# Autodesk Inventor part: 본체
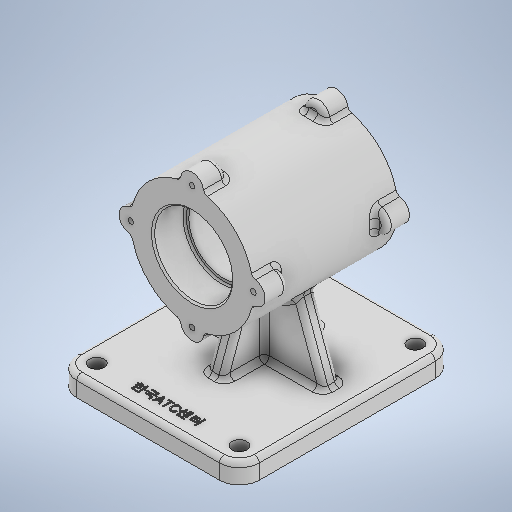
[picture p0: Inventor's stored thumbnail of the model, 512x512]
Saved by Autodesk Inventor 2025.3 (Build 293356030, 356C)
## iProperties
Created: 2025-08
Part Number: 본체
Material: 일반
Document SubType Name: Modeling
Designer: user
Density: 1 g/cm^3
Appearance: 기본값
Author: user
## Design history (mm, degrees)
sketch "스케치2"
  geometry: L1 (43, 65)-(-43, 65); L2 (-55, 53)-(-55, -53); L3 (-43, -65)-(43, -65); L4 (55, -53)-(55, 53); L5 (55, 65)-(-55, -65); L6 (-55, 65)-(55, -65); A1 r 12 centre (43, 53) between (55, 53) and (43, 65); A2 r 12 centre (-43, 53) between (-43, 65) and (-55, 53); A3 r 12 centre (43, -53) between (43, -65) and (55, -53); A4 r 12 centre (-43, -53) between (-55, -53) and (-43, -65); 1 further point
  constraints: 12 end point, 8 point on circle, 8 point on line, 8 tangent, 4 centre point, 3 equal radius, 2 midpoint, 2 parallel, 1 horizontal, 1 perpendicular
  dimensions: "d0" = 130 distance between parallel lines of L3 L1; "d1" = 110 distance between parallel lines of L4 L2; "d2" = 12 radius of A1
extrude "돌출1" new body sketch "스케치2" distance "d3" = 12; taper "d4" = 0 deg
sketch "스케치3"
  geometry: L1 (-43, -53)-(43, -53); L2 (43, -53)-(43, 53); L3 (43, 53)-(-43, 53); L4 (-43, 53)-(-43, -53); L5 (-43, -53)-(43, 53); L6 (43, -53)-(-43, 53); 1 further point
  constraints: 12 end point, 2 midpoint, 2 parallel, 1 horizontal, 1 perpendicular
  dimensions: "d5" = 86 distance of L3.end L2.end; "d6" = 106 distance of L2.end L1.end
hole "구멍1" sketch "스케치3" at (43, -53), (-43, -53), (-43, 53), (43, 53) diameter "d7" = 9; stored, may be unused: countersink angle "d11" = 90 deg, drill point angle "d13" = 118 deg; dims "d8" = 6, "d9" = 4, "d10" = 2, "d12" = 8
sketch "스케치4"
  geometry: L1 (119, 38.5)-(82, 38.5); L2 (82, 38.5)-(82, -48.5); L3 (82, -48.5)-(119, -48.5); L4 (119, -48.5)-(119, 38.5); L5 (0, 53)-(0, -53) reference; L6 (0, 65)-(12, 65) reference; L7 (82, 38.5)-(105.5, 38.5); L8 (105.5, 38.5)-(105.5, 19.5); L9 (105.5, 19.5)-(82, 19.5); L10 (82, 19.5)-(82, 38.5); L11 (82, -48.5)-(105.5, -48.5); L12 (105.5, -48.5)-(105.5, -29.5); L13 (105.5, -29.5)-(82, -29.5); L14 (82, -29.5)-(82, -48.5); L15 (82, 19.5)-(103, 19.5); L16 (103, 19.5)-(103, -29.5); L17 (103, -29.5)-(82, -29.5); L18 (82, -29.5)-(82, 19.5); 6 further points
  constraints: 32 end point, 8 parallel, 4 horizontal, 4 perpendicular, 2 midpoint, 1 point on line
  dimensions: "d14" = 37 distance of L3.end L2.end; "d15" = 87 distance of L2.end L1.end; "d16" = 82 distance between parallel lines of L5 L2; "d17" = 70 vertical distance of point (6, 65) point (119, -5); "d18" = 23.5 distance of L8.end L9.end; "d19" = 19 distance of L7.end L8.end; "d20" = 23.5 distance of L13.end L12.end; "d21" = 19 distance of L12.end L11.end; "d22" = 21 distance of L16.end L17.end
revolve "회전1" sketch "스케치4" stored, may be unused: angle "d23" = 90 deg
sketch "스케치5"
  geometry: L1 (0, 0)-(0, 37); C1 r 7 at (0, 37); C2 r 7 at (-37, 0); C3 r 7 at (0, -37); C4 r 7 at (37, 0); 2 further points
  constraints: 4 centre point, 2 end point, 1 coincident, 1 vertical, 1 vertical alignment, 10 other
  dimensions: "d25" = 0 distance from line of point (0, 0) L1; "d26" = 0 distance of L1.start point (0, 0); "d31" = 14 diameter of C1; "d34" = 360 deg dimension on L1.start C1.centre (derived)
extrude "돌출2" join sketch "스케치5" distance "d36" = 14; taper "d37" = 0 deg
sketch "스케치7"
  geometry: A1 r 7 centre (0, 0) between (6.969, -0.662) and (-6.969, -0.662) reference; A2 r 7 centre (37, -37) between (36.338, -43.969) and (36.338, -30.031) reference; A3 r 7 centre (0, -74) between (-6.969, -73.338) and (6.969, -73.338) reference; A4 r 7 centre (-37, -37) between (-36.338, -30.031) and (-36.338, -43.969) reference; 1 further point
hole "구멍2" sketch "스케치7" at (-37, -37), (0, -74), (0, 0), (37, -37) diameter "d38" = 3.242; stored, may be unused: countersink angle "d42" = 90 deg, drill point angle "d44" = 118 deg; dims "d39" = 8, "d40" = 4, "d41" = 2, "d43" = 10
node "작업 평면1"
sketch "스케치8"
  geometry: L1 (-43, -65)-(43, -65) reference; L2 (0, -65)-(0, 5); L3 (0, -65)-(70, -65); L4 (-5, 0)-(5, 0); L5 (5, 0)-(5, 10); L6 (5, 10)-(-5, 10); L7 (-5, 10)-(-5, 0); L8 (-5, 0)-(5, 10); L9 (5, 0)-(-5, 10); 1 further point
  constraints: 16 end point, 3 midpoint, 2 horizontal, 2 parallel, 2 perpendicular, 1 vertical
  dimensions: "d46" = 70 distance of L2.start L2.end; "d47" = 90 deg angle of L3 L2 (derived); "d48" = 10 distance of L6.end L5.end; "d49" = 10 distance of L5.end L4.end
extrude "돌출3" join sketch "스케치8" stored distance "d50" = 0; taper "d51" = 0 deg
node "작업 평면2"
sketch "스케치12"
  geometry: L1 (55, 12)-(43, 12) reference; L2 (55, 12)-(41, 12); L3 (38.5, 12)-(47.5, 12) reference; L4 (41, 12)-(25.336, 55.036); A1 r 37 centre (0, 82) between (6.969, 45.662) and (36.338, 75.031) reference; 1 further point
  constraints: 4 end point, 1 point on circle, 1 point on line
  dimensions: "d60" = 14 distance of L1.start L2.end; "d61" = 110 deg angle of L4 L1
feature "리브1" sketch "스케치12" dims "d62" = 1, "d63" = 10, "d64" = 0, "d65" = 0, "d66" = 1, "d67" = 1
sketch "스케치14"
  geometry: L1 (45, 24.5)-(45, -34.5) reference; L2 (12, -65)-(12, -53) reference; L3 (12, -65)-(12, -35); L4 (12, 53)-(12, -53) reference; L5 (12, -35)-(45, -22.989); 2 further points
  constraints: 4 end point, 3 point on line
  dimensions: "d73" = 110 deg angle of L3 L5; "d74" = 30 distance of L2.start L3.end; "d94" = 60 distance of L3.end point (12, 25)
feature "리브2" sketch "스케치14" dims "d75" = 1, "d76" = 10, "d77" = 0, "d78" = 0, "d79" = 1, "d80" = 1
fillet "모깎기1" dims "d81" = 1
fillet "모깎기2" dims "d82" = 3
fillet "모깎기3" dims "d83" = 3
sketch "스케치15"
  geometry: L1 (-13.888, -49.998)-(13.888, -49.998); L2 (13.888, -49.998)-(13.888, -56.002); L3 (13.888, -56.002)-(-13.888, -56.002); L4 (-13.888, -56.002)-(-13.888, -49.998); L5 (77, 5)-(-77, 5) reference; L6 (6.889, -27.5)-(-6.889, -27.5) reference; 4 further points
  constraints: 3 midpoint, 2 other
  dimensions: "d84" = 58 distance from line of L5 point (13.888, -53); "d85" = 0 horizontal distance of point (0, -49.998) point (0, -27.5)
feature "엠보싱1" sketch "스케치15" dims "d0" = 130, "d1" = 110, "d2" = 12, "d7" = 9, "d86" = 0.5, "d87" = 0
chamfer "모따기1" distance "d88" = 1; stored, may be unused: second distance "d89" = 2, angle "d90" = 45 deg
chamfer "모따기2" distance "d91" = 1; stored, may be unused: second distance "d92" = 2, angle "d93" = 45 deg
node "솔리드1"
mirror "미러1"
mirror "미러2"
mirror "미러3"
node "스케치 - 원형 패턴2" dims "d34" = 360 deg (derived)
feature "A9D066F2-1C7D-4E18-AEED-F7BC21143FA4" dims "d7" = 9, "d8" = 6, "d9" = 4, "d10" = 2, "d11" = 90 deg, "d12" = 8, "d13" = 118 deg
other parameters: "d45" = -43.5, "d59" = -5
